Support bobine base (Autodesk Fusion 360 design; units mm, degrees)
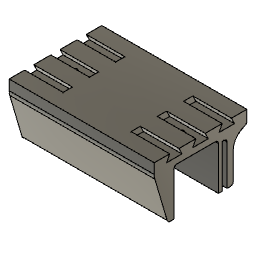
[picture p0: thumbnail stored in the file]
sketch "Esquisse1" plane through (0, 0, 0) normal (1, 0, 0) x axis (0, 1, 0)
  line L1 (21.2, 38) -> (-21.2, 38)
  line L2 (17.2, 0) -> (21.2, 0)
  line L3 (17.2, 28) -> (17.2, 0)
  line L4 (14, 0) -> (14, 28)
  line L5 (11.6, 0) -> (14, 0)
  line L6 (11.6, 30) -> (11.6, 0)
  line L7 (-17.2, 0) -> (-17.2, 30)
  line L8 (-21.2, 0) -> (-17.2, 0)
  line L9 (-21.2, 38) -> (-21.2, 0)
  line L10 (21.2, 38) -> (21.2, 0)
  line L11 (11.6, 30) -> (-17.2, 30)
  line L12 (17.2, 28) -> (14, 28)
  line L13 (-30, 38) -> (-21.2, 38)
  line L14 (30, 38) -> (21.2, 38)
  line L15 (27, 26) -> (21.2, 26)
  line L16 (30, 30) -> (30, 38)
  line L17 (21.2, 26) -> (30, 30)
  line L18 (-30, 30) -> (-30, 38)
  line L19 (-21.2, 0) -> (-30, 30)
  point P3 (21.2, 38)
  point P14 (21.2, 38)
  point P17 (21.2, 26)
  point P11 (-17.2, 30)
  point P12 (-17.2, 0)
  point P2 (-21.2, 38)
  point P13 (-21.2, 0)
  point P8 (14, 0)
  point P9 (11.6, 0)
  point P4 (21.2, 0)
  point P5 (17.2, 0)
  point P1 (0, 0)
  point P6 (17.2, 28)
  point P7 (14, 28)
  point P10 (11.6, 30)
  point P15 (-30, 38)
  point P16 (30, 38)
  point P19 (30, 30)
  point P20 (-30, 30)
  collinear L5 L8
  collinear L2 L8
  horizontal L1
  perpendicular L7 L11
  perpendicular L3 L12
  perpendicular L6 L11
  perpendicular L1 L9
  perpendicular L1 L10
  perpendicular L4 L12
  perpendicular L2 L10
  perpendicular L2 L3
  coincident P3 P14
  perpendicular L9 L13
  perpendicular L10 L14
  coincident L10 P17
  perpendicular L10 L15
  perpendicular L11 L18
  perpendicular L14 L16
  dimension "d3" distance P11 P12 = 30
  dimension "d4" distance P2 P13 = 38
  dimension "d5" distance P12 P13 = 4
  dimension "d6" distance P8 P9 = 2.4
  dimension "d7" distance P4 P5 = 4
  dimension "d8" distance P2 P3 = 42.4
  dimension "d9" distance P1 L1 = 38
  dimension "d10" distance P6 P7 = 3.2
  dimension "d11" distance P10 P11 = 28.8
  dimension "d12" distance P1 P13 = 21.2
  dimension "d21" distance P1 L12 = 28
  dimension "d24" distance P2 P15 = 8.8
  dimension "d25" distance P14 P16 = 8.8
  dimension "d26" distance L14 L15 = 12
  dimension "d59" distance L14 P19 = 8
  dimension "d64" distance P15 P20 = 8
extrude "Extrusion1" new body sketch "Esquisse1" profile of L1 L2 L3 L4 L5 L6 L7 L8 L9 L10 L11 L12 L13 L14 L16 L17 L18 L19 distance 47
sketch "Esquisse3" plane through (0, 11.6, 0) normal (0, -1, 0) x axis (1, 0, 0)
  line L1 (5, -2) -> (5, 30)
  line L2 (-33, -2) -> (-33, 30)
  line L3 (-47, -2) -> (-47, 30)
  line L4 (-33, 30) -> (-47, 30)
  line L5 (5, 30) -> (-14, 30)
  line L6 (-33, -2) -> (-47, -2)
  line L7 (5, -2) -> (-14, -2)
  line L8 (-14, -2) -> (-14, 30)
  line L9 (47, 38) -> (-47, 38)
  line L10 (-47, 0) -> (47, 0)
  line L11 (47, 0) -> (47, 30)
  line L12 (47, 30) -> (-47, 30)
  line L13 (47, 38) -> (47, 30)
  line L14 (-47, 38) -> (47, 38)
  line L15 (-47, 30) -> (-47, 38)
  line L16 (47, 0) -> (-47, 0)
  line L17 (47, 30) -> (47, 0)
  line L18 (-47, 30) -> (47, 30)
  line L19 (-47, 0) -> (-47, 30)
  point P3 (-14, 30)
  point P9 (-14, -2)
  point P6 (5, -2)
  point P8 (-33, -2)
  point P7 (-47, -2)
  coincident P3 L4
  perpendicular L2 L4
  perpendicular L3 L4
  perpendicular L1 L6
  coincident P9 L6
  collinear L4 L5
  collinear L6 L7
  perpendicular L7 L8
  dimension "d38" distance P6 P9 = 19
  dimension "d39" distance P8 P9 = 19
  dimension "d40" distance L4 L6 = 32
  dimension "d65" distance L4 L14 = 8
  dimension "d66" distance L1 L17 = 42
  dimension "d67" distance P7 P8 = 14
extrude "Extrusion2" cut sketch "Esquisse3" profile of L5 L1 L2 L3 L7 to an object
sketch "Esquisse5" plane through (0, 0, 0) normal (1, 0, 0) x axis (0, 1, 0)
  line L1 (21.2, 22.7263) -> (21.2, 2)
  line L2 (30, 38) -> (23.136, 28.6399)
  line L3 (-30, 38) -> (30, 38)
  line L4 (-21.5587, 1.5488) -> (-30, 38)
  line L5 (-17.2, 0) -> (-19.6102, 0)
  line L6 (-17.2, 28) -> (-17.2, 0)
  line L7 (9.6, 30) -> (-15.2, 30)
  line L8 (11.6, 0) -> (11.6, 28)
  line L9 (14, 0) -> (11.6, 0)
  line L10 (14, 28) -> (14, 0)
  line L11 (15.2, 28) -> (14, 28)
  line L12 (17.2, 0) -> (17.2, 26)
  line L13 (19.2, 0) -> (17.2, 0)
  line L14 (0, 38) -> (0, 0)
  line L15 (30, 34) -> (-30, 34)
  line L16 (-30, 38) -> (30, 38)
  line L17 (-3, 38) -> (-5, 34)
  line L18 (3, 38) -> (5, 34)
  line L19 (3, 38) -> (-3, 38)
  line L20 (5, 34) -> (-5, 34)
  line L21 (-20, 38) -> (-22, 34)
  line L22 (-14, 38) -> (-12, 34)
  line L23 (-12, 34) -> (-22, 34)
  line L24 (-14, 38) -> (-20, 38)
  line L25 (14, 38) -> (12, 34)
  line L26 (20, 38) -> (22, 34)
  line L27 (22, 34) -> (12, 34)
  line L28 (20, 38) -> (14, 38)
  line L29 (30, 38) -> (-30, 38)
  line L30 (-29.0737, 34) -> (27.0667, 34)
  arc A1 centre (19.2, 2) radius 2 clockwise from (21.2, 2) to (19.2, 0)
  arc A2 centre (31.2, 22.7263) radius 10 clockwise from (21.2, 22.7263) to (23.136, 28.6399)
  arc A3 centre (-19.6102, 2) radius 2 clockwise from (-19.6102, 0) to (-21.5587, 1.5488)
  arc A4 centre (-15.2, 28) radius 2 clockwise from (-17.2, 28) to (-15.2, 30)
  arc A5 centre (9.6, 28) radius 2 clockwise from (9.6, 30) to (11.6, 28)
  arc A6 centre (15.2, 26) radius 2 clockwise from (15.2, 28) to (17.2, 26)
  point P1 (0, 0)
  point P27 (0, 0)
  point P29 (-30, 34)
  point P32 (-30, 38)
  point P28 (0, 38)
  point P33 (-5, 34)
  point P34 (-3, 38)
  point P35 (5, 34)
  point P36 (3, 38)
  point P47 (27.0667, 34)
  point P48 (-29.0737, 34)
  coincident P1 P27
  perpendicular L3 L14
  horizontal L15
  equal L3 L15
  vertical P29 P32
  coincident P28 L16
  coincident L15 P33
  coincident L16 P34
  symmetric L14 P33 P35
  symmetric L14 P34 P36
  coincident L2 P47
  coincident L15 P47
  coincident L15 P48
  coincident L4 P48
  dimension "d48" distance L15 L16 = 4
  dimension "d50" distance P28 P34 = 3
  dimension "d51" distance P28 P33 = 5
  dimension "d54" R-Pattern1-uDistance = 17
  dimension "d55" R-Pattern1-vDistance = 0
extrude "Extrusion3" cut sketch "Esquisse5" profile of L3 L16 L17 L18 L19 L20 L21 L22 L23 L24 L25 L26 L27 L28 L29 L30 no distance stored
extrude "Extrusion4" add sketch "Esquisse5" profile of L3 L16 L17 L18 L19 L20 L21 L22 L23 L24 L25 L26 L27 L28 L29 L30 distance 22
fillet "Congé10" radius 2
fillet "Congé11" radius 10
sketch "Esquisse8" plane through (0, 0, 34) normal (0, 0, 1) x axis (-1, 0, 0)
  line L1 (22, -5) -> (22, 5)
  line L2 (47, -5) -> (22, -5)
  line L3 (47, 5) -> (47, -5)
  line L4 (22, 5) -> (47, 5)
  line L5 (22, -20) -> (47, -20)
  line L6 (22, -14) -> (22, -20)
  line L7 (47, -14) -> (22, -14)
  line L8 (47, -3) -> (47, -14)
  line L9 (22, -3) -> (47, -3)
  line L10 (22, 3) -> (22, -3)
  line L11 (47, 3) -> (22, 3)
  line L12 (47, 14) -> (47, 3)
  line L13 (22, 14) -> (47, 14)
  line L14 (22, 20) -> (22, 14)
  line L15 (47, 20) -> (22, 20)
  line L16 (47, 30) -> (47, 20)
  line L17 (-47, 30) -> (47, 30)
  line L18 (-47, 20) -> (-47, 30)
  line L19 (-22, 20) -> (-47, 20)
  line L20 (-22, 14) -> (-22, 20)
  line L21 (-47, 14) -> (-22, 14)
  line L22 (-47, 3) -> (-47, 14)
  line L23 (-22, 3) -> (-47, 3)
  line L24 (-22, -3) -> (-22, 3)
  line L25 (-47, -3) -> (-22, -3)
  line L26 (-47, -14) -> (-47, -3)
  line L27 (-22, -14) -> (-47, -14)
  line L28 (-22, -20) -> (-22, -14)
  line L29 (-47, -20) -> (-22, -20)
  line L30 (-47, -30) -> (-47, -20)
  line L31 (47, -30) -> (-47, -30)
  line L32 (47, -20) -> (47, -30)
  circle C1 centre (34.5, 0) radius 1.7
  circle C2 centre (-34.5, 0) radius 1.7
  point P34 (34.5, 0)
  point P35 (-34.5, 0)
  dimension "d75" diameter C1 = 3.4
  dimension "d76" diameter C2 = 3.4
  dimension "d77" distance L3 P34 = 12.5
  dimension "d78" distance L31 P34 = 30
  dimension "d79" distance L22 P35 = 12.5
  dimension "d80" distance L31 P35 = 30
extrude "Extrusion5" cut sketch "Esquisse8" profile of C1 C2 no distance stored
sketch "Esquisse9" plane through (0, 0, 30) normal (0, 0, -1) x axis (1, 0, 0)
  line L1 (47, -9.6) -> (5, -9.6)
  line L2 (47, 15.2) -> (47, -9.6)
  line L3 (-47, 15.2) -> (47, 15.2)
  line L4 (-47, -14) -> (-47, 15.2)
  line L5 (-14, -14) -> (-14, -9.6)
  line L6 (5, -14) -> (-14, -14)
  line L7 (5, -9.6) -> (5, -14)
  line L8 (-33, -14) -> (-47, -14)
  line L9 (-33, -9.6) -> (-33, -14)
  line L10 (-14, -9.6) -> (-33, -9.6)
  circle C1 centre (-34.5, 0) radius 1.7
  circle C2 centre (34.5, 0) radius 1.7
  circle C3 centre (34.5, 0) radius 3.25
  circle C4 centre (-34.5, 0) radius 3.25
  concentric C2 C3
  concentric C1 C4
  dimension "d82" diameter C3 = 6.5
  dimension "d83" diameter C4 = 6.5
extrude "Extrusion6" cut sketch "Esquisse9" profile of C1 C2 C3 C4 against normal blind 2
sketch "Esquisse10" plane through (0, 21.2, 0) normal (0, 1, 0) x axis (-1, 0, 0)
  line L1 (-47, 19.5609) -> (47, 19.5609)
  line L2 (-47, 2) -> (-47, 19.5609)
  line L3 (47, 2) -> (-47, 2)
  line L4 (47, 19.5609) -> (47, 2)
  line L5 (36, -2) -> (28, -2)
  line L6 (36, 13) -> (36, -2)
  line L7 (28, 13) -> (36, 13)
  line L8 (28, -2) -> (28, 13)
  line L9 (47, 0) -> (-47, 0)
  line L10 (47, 2) -> (47, 19.5609)
  point P6 (28, -2)
  point P7 (36, -2)
  point P8 (36, 13)
  horizontal L5
  vertical L6
  horizontal L7
  vertical L8
  dimension "d86" distance P6 P7 = 8
  dimension "d87" distance P7 P8 = 15
  dimension "d88" distance L7 L9 = 13
  dimension "d89" distance L6 L10 = 11
extrude "Extrusion7" cut sketch "Esquisse10" profile of L3 L5 L6 L7 L8 L9 to an object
